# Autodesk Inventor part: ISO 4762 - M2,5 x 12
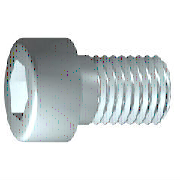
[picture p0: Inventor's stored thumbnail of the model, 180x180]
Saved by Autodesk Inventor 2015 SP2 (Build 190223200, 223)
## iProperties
IsCustomPart: 0
Created: 2012-02
Part Number: ISO 4762 - M2,5 x 12
Material: Edelstahl, 440C
Description: Innensechskantschraube
Document SubType Name: Modeling
Standard: ISO 4762
Designer: rYan
Standard Revision: 1998
Standards Organization: DIN
Language: de-DE
Size Designation: M2,5 x 12
Categories: <MemberInstance><Categories><Category DisplayName="Verbindungselemente" InternalName="e4da775c-781d-43d5-af7c-5136215cf5a6" Mnemonic="FSTN"><Category DisplayNam
Density: 7.75 g/cm^3
Appearance: Halbpoliert
Author: rYan
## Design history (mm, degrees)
sketch "Skizze1"
  geometry: L1 (-0.733, 0)-(12, 0); L2 (12, 0)-(12, 1.25); L3 (12, 1.25)-(1.125, 1.25); L4 (1.125, 1.25)-(0.849, 1.25); L5 (0.849, 1.25)-(0, 1.25); L6 (0, 1.25)-(0, 2.25); L7 (0, 2.25)-(-2.5, 2.25); L8 (-2.5, 2.25)-(-2.5, 1.155); L9 (-2.5, 1.155)-(-1.4, 1.155); L10 (-1.4, 1.155)-(-0.733, 0); L11 (-5.4, 0)-(14.9, 0) reference; L12 (0, -0.45)-(0, 2.7) reference; L13 (1.125, 1.25)-(0, 1.25)
  constraints: 22 end point, 6 parallel, 2 collinear, 2 perpendicular, 1 horizontal, 1 point on line
  dimensions: "d1" = 10.875 distance from line of L3.end L2 (= GEL); "d2" = 0.27615 distance of L4.end L3.end (computed from GAL); "d3" = 2.5 distance between parallel lines of L8 L6 (= KOH); "d4" = 1.1 distance of L8.end L9.end (= INTI); "d5" = 60 deg angle of L10 L1; "d6" = 2.5 diameter of L3 L1 (= GD); "d7" = 2.5 diameter of L5 L1 (= BDM); "d8" = 2.3094 diameter of L9 L1 (= 1.1547 x SW); "d9" = 4.5 diameter of L7 L1 (= KOD); "d26" = 12 distance between parallel lines of L12 L2 (= NLG)
revolve "Körper" sketch "Skizze1" stored, may be unused: angle "d10" = 90 deg
sketch "Skizze2"
  geometry: L1 (0, -3.15)-(0, 3.15) reference; L2 (-3.15, 0)-(3.15, 0) reference; L3 (1.155, 0)-(0.577, -1); L4 (0.577, -1)-(-0.577, -1); L5 (-0.577, -1)-(-1.155, 0); L6 (-1.155, 0)-(-0.577, 1); L7 (-0.577, 1)-(0.577, 1); L8 (0.577, 1)-(1.155, 0); 2 further points
  constraints: 12 end point, 1 coincident, 1 horizontal alignment, 1 point on line, 12 other
extrude "Loch" join sketch "Skizze2" stored distance "d11" = 10; taper "d12" = 0 deg
workplane "Work Plane1"
fillet "Fillet2" dims "d30" = 0.1 (= R)
body "Solid1"
fillet "Rundung1" dims "d17" = 0.25 (= RR)
feature "Gewinde" dims "d13" = 10.875 (= GEL), "d14" = 0
chamfer "Fase1" distance "d15" = 0.27605 (= -0.5 x SPD + 0.5 x GD); stored, may be unused: second distance "d16" = 0.27605 (= GUL), angle "d27" = 45 deg
other parameters: "GD" = 2.5 [user parameter; used in 2 equation terms], "NLG" = 12 [user parameter; used in 1 equation term], "GEL" = 10.875 [user parameter; used in 2 equation terms], "KOD" = 4.5 [user parameter; used in 1 equation term], "KOH" = 2.5 [user parameter; used in 1 equation term], "INTI" = 1.1 [user parameter; used in 1 equation term], "GAL" = 0.27605 (= 0.61345 x PTC) [user parameter; used in 1 equation term], "GUL" = 0.27605 (= 0.61345 x PTC) [user parameter; used in 1 equation term], "BDM" = 2.5 (= NND) [user parameter; used in 1 equation term], "SW" = 2 [user parameter; used in 2 equation terms], "RR" = 0.25 [user parameter; used in 1 equation term], "SPD" = 1.94789 (= NND - 1.2269 x PTC) [user parameter; used in 1 equation term], "d19" = 0, "d28" = 0, "d29" = 0, "R" = 0.1 [user parameter; used in 1 equation term], "TOA" = 30 deg [user parameter], "GD1" = 1.94789 (= THREADDIA - 1.2269 x PTC) [user parameter], "THREADDIA" = 2.5 [user parameter; used in 1 equation term], "FAWI" = 45 deg [user parameter], "TPU" = 22.22222 (computed from PTC) [user parameter], "PTC" = 0.45 [user parameter; used in 5 equation terms], "NND" = 2.5 [user parameter; used in 2 equation terms], "E0" = 2.31 (= 1.155 x SW) [user parameter]
